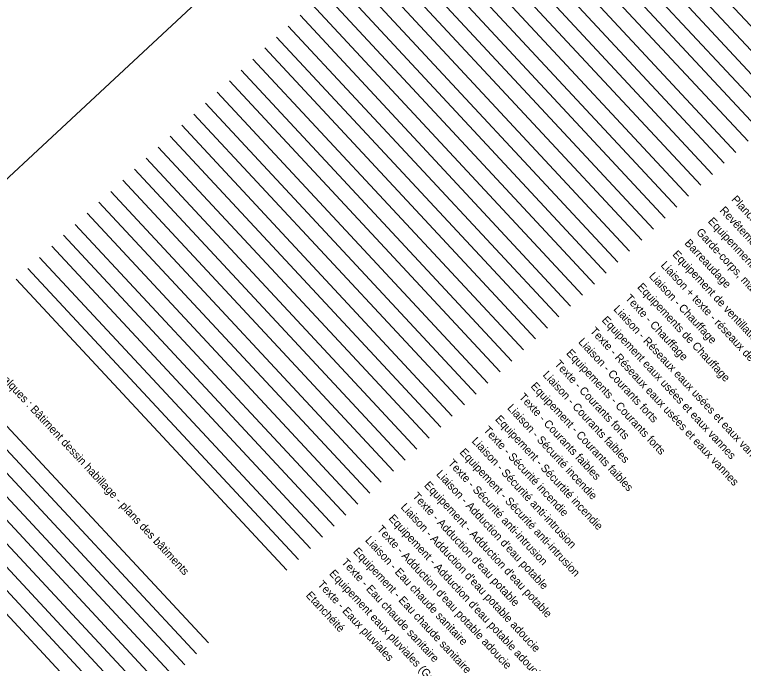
# Model space of a CAD drawing. Extents: x 704383 to 706615, y 7057567 to 7059313.
# Drawn here: x 706521.46 to 706566.99, y 7057633.3 to 7057673.83 of the extents above; entities that cross this region are included whole.
import ezdxf

# ---------------------------------------------------------------- set-up
doc = ezdxf.new("R2010")
doc.units = 0
for name, color, linetype in [('BAT_DH_CALEPINAGE_FACADE', 7, 'Continuous'), ('BAT_DH_COTATION', 7, 'Continuous'), ('BAT_DH_COTATION_NGF', 7, 'Continuous'), ('BAT_DH_EQUIP INTERIEUR', 7, 'Continuous'), ('BAT_DH_HACHURE-MOTIF', 7, 'Continuous'), ('BAT_DH_PERSONNAGE_VEHICULES', 7, 'Continuous'), ('BAT_DH_TEXTE', 7, 'Continuous'), ('BAT_DH_TRAIT CONSTRUCTION', 7, 'Continuous'), ('BAT_DH_TRAIT DE COUPE', 7, 'Continuous'), ('DH_CADRE -CARTOUCHE', 7, 'Continuous'), ('GO_COUVERTURE', 7, 'Continuous'), ('SO_AEP_AD_EQUIP', 7, 'Continuous'), ('SO_AEP_AD_LIAISON', 7, 'Continuous'), ('SO_AEP_AD_TEXTE', 7, 'Continuous'), ('SO_AEP_EQUIP', 7, 'Continuous'), ('SO_AEP_LIAISON', 7, 'Continuous'), ('SO_AEP_TEXTE', 7, 'Continuous'), ('SO_ANTI_INTRUSION_EQUIP', 7, 'Continuous'), ('SO_ANTI_INTRUSION_LIAISON', 7, 'Continuous'), ('SO_ANTI_INTRUSION_TEXTE', 7, 'Continuous'), ('SO_BARREAUDAGE', 7, 'Continuous'), ('SO_CHAUFFAGE_EQUIP', 7, 'Continuous'), ('SO_CHAUFFAGE_LIAISON', 7, 'Continuous'), ('SO_CHAUFFAGE_TEXTE', 7, 'Continuous'), ('SO_ECS_EQUIP', 7, 'Continuous'), ('SO_ECS_LIAISON', 7, 'Continuous'), ('SO_ECS_TEXTE', 7, 'Continuous'), ('SO_ELEC_C_FAIBLES_EQUIP', 7, 'Continuous'), ('SO_ELEC_C_FAIBLES_LIAISON', 7, 'Continuous'), ('SO_ELEC_C_FAIBLES_TEXTE', 7, 'Continuous'), ('SO_ELEC_C_FORTS_EQUIP', 7, 'Continuous'), ('SO_ELEC_C_FORTS_LIAISON', 7, 'Continuous'), ('SO_ELEC_C_FORTS_TEXTE', 7, 'Continuous'), ('SO_EP_EQUIP', 7, 'Continuous'), ('SO_EP_TEXTE', 7, 'Continuous'), ('SO_EU_EV_EQUIP', 7, 'Continuous'), ('SO_EU_EV_LIAISON', 7, 'Continuous'), ('SO_EU_EV_TEXTE', 7, 'Continuous'), ('SO_GARDE_CORPS', 7, 'Continuous'), ('SO_MENUISERIE DIVERS_TEXTE', 7, 'Continuous'), ('SO_MENUISERIE EXT_ EQUIP', 7, 'Continuous'), ('SO_MENUISERIE EXT_TEXTE', 7, 'Continuous'), ('SO_MENUISERIE EXT_TYPE', 7, 'Continuous'), ('SO_MENUISERIE INT_ EQUIP', 7, 'Continuous'), ('SO_MENUISERIE INT_TEXTE', 7, 'Continuous'), ('SO_MENUISERIE INT_TYPE', 7, 'Continuous'), ('SO_PLAFOND', 7, 'Continuous'), ('SO_PLANCHER TECHNIQUE', 7, 'Continuous'), ('SO_REVETEMENT_SOL_MUR', 7, 'Continuous'), ('SO_SANITAIRE', 7, 'Continuous'), ('SO_SECU_INCENDIE_EQUIP', 7, 'Continuous'), ('SO_SECU_INCENDIE_LIAISON', 7, 'Continuous'), ('SO_SECU_INCENDIE_TEXTE', 7, 'Continuous'), ('SO_VMC_CVC_CTA_EQUIP', 7, 'Continuous'), ('SO_VMC_CVC_CTA_RES-TEXTE', 7, 'Continuous')]:
    doc.layers.add(name, color=color, linetype=linetype)

msp = doc.modelspace()

# ---------------------------------------------------------------- linework, layer by layer
at = {"layer": 'BAT_DH_CALEPINAGE_FACADE'}
msp.add_line((706516.66, 7057652.746), (706533.566, 7057634.574), dxfattribs=at)
at = {"layer": 'BAT_DH_COTATION'}
msp.add_line((706515.927, 7057652.065), (706532.833, 7057633.893), dxfattribs=at)
at = {"layer": 'BAT_DH_COTATION_NGF'}
msp.add_line((706515.195, 7057651.383), (706532.101, 7057633.211), dxfattribs=at)
at = {"layer": 'BAT_DH_EQUIP INTERIEUR'}
msp.add_line((706514.463, 7057650.702), (706531.369, 7057632.53), dxfattribs=at)
at = {"layer": 'BAT_DH_HACHURE-MOTIF'}
msp.add_line((706513.731, 7057650.021), (706530.637, 7057631.849), dxfattribs=at)
at = {"layer": 'BAT_DH_PERSONNAGE_VEHICULES'}
msp.add_line((706512.999, 7057649.34), (706529.905, 7057631.168), dxfattribs=at)
at = {"layer": 'BAT_DH_TEXTE'}
msp.add_line((706512.267, 7057648.659), (706529.173, 7057630.487), dxfattribs=at)
at = {"layer": 'BAT_DH_TRAIT CONSTRUCTION'}
msp.add_line((706511.534, 7057647.978), (706528.441, 7057629.806), dxfattribs=at)
at = {"layer": 'BAT_DH_TRAIT DE COUPE'}
msp.add_line((706510.802, 7057647.297), (706527.708, 7057629.124), dxfattribs=at)
at = {"layer": 'DH_CADRE -CARTOUCHE'}
msp.add_lwpolyline([(706573.792, 7057712.707), (706614.66, 7057668.778), (706534.124, 7057593.852), (706493.255, 7057637.781)], close=True, dxfattribs=at)
at = {"layer": 'GO_COUVERTURE'}
msp.add_line((706521.562, 7057657.297), (706538.475, 7057639.118), dxfattribs=at)
at = {"layer": 'SO_AEP_AD_EQUIP'}
msp.add_line((706526.733, 7057662.107), (706543.645, 7057643.928), dxfattribs=at)
at = {"layer": 'SO_AEP_AD_LIAISON'}
msp.add_line((706527.465, 7057662.788), (706544.368, 7057644.62), dxfattribs=at)
at = {"layer": 'SO_AEP_AD_TEXTE'}
msp.add_line((706526.001, 7057661.426), (706542.913, 7057643.247), dxfattribs=at)
at = {"layer": 'SO_AEP_EQUIP'}
msp.add_line((706528.952, 7057664.172), (706545.865, 7057645.993), dxfattribs=at)
at = {"layer": 'SO_AEP_LIAISON'}
msp.add_line((706529.684, 7057664.853), (706546.587, 7057646.685), dxfattribs=at)
at = {"layer": 'SO_AEP_TEXTE'}
msp.add_line((706528.22, 7057663.491), (706545.132, 7057645.312), dxfattribs=at)
at = {"layer": 'SO_ANTI_INTRUSION_EQUIP'}
msp.add_line((706531.171, 7057666.236), (706548.084, 7057648.058), dxfattribs=at)
at = {"layer": 'SO_ANTI_INTRUSION_LIAISON'}
msp.add_line((706531.903, 7057666.918), (706548.806, 7057648.75), dxfattribs=at)
at = {"layer": 'SO_ANTI_INTRUSION_TEXTE'}
msp.add_line((706530.439, 7057665.555), (706547.352, 7057647.376), dxfattribs=at)
at = {"layer": 'SO_BARREAUDAGE'}
msp.add_line((706545.196, 7057679.284), (706562.098, 7057661.116), dxfattribs=at)
at = {"layer": 'SO_CHAUFFAGE_EQUIP'}
msp.add_line((706542.244, 7057676.538), (706559.147, 7057658.37), dxfattribs=at)
at = {"layer": 'SO_CHAUFFAGE_LIAISON'}
msp.add_line((706542.976, 7057677.219), (706559.879, 7057659.051), dxfattribs=at)
at = {"layer": 'SO_CHAUFFAGE_TEXTE'}
msp.add_line((706541.512, 7057675.857), (706558.425, 7057657.678), dxfattribs=at)
at = {"layer": 'SO_ECS_EQUIP'}
msp.add_line((706524.514, 7057660.043), (706541.426, 7057641.864), dxfattribs=at)
at = {"layer": 'SO_ECS_LIAISON'}
msp.add_line((706525.246, 7057660.724), (706542.148, 7057642.556), dxfattribs=at)
at = {"layer": 'SO_ECS_TEXTE'}
msp.add_line((706523.782, 7057659.362), (706540.694, 7057641.183), dxfattribs=at)
at = {"layer": 'SO_ELEC_C_FAIBLES_EQUIP'}
msp.add_line((706535.61, 7057670.366), (706552.522, 7057652.187), dxfattribs=at)
at = {"layer": 'SO_ELEC_C_FAIBLES_LIAISON'}
msp.add_line((706536.342, 7057671.047), (706553.244, 7057652.879), dxfattribs=at)
at = {"layer": 'SO_ELEC_C_FAIBLES_TEXTE'}
msp.add_line((706534.877, 7057669.684), (706551.79, 7057651.506), dxfattribs=at)
at = {"layer": 'SO_ELEC_C_FORTS_EQUIP'}
msp.add_line((706537.829, 7057672.43), (706554.741, 7057654.251), dxfattribs=at)
at = {"layer": 'SO_ELEC_C_FORTS_LIAISON'}
msp.add_line((706538.561, 7057673.111), (706555.463, 7057654.943), dxfattribs=at)
at = {"layer": 'SO_ELEC_C_FORTS_TEXTE'}
msp.add_line((706537.097, 7057671.749), (706554.009, 7057653.57), dxfattribs=at)
at = {"layer": 'SO_EP_EQUIP'}
msp.add_line((706523.027, 7057658.659), (706539.939, 7057640.48), dxfattribs=at)
at = {"layer": 'SO_EP_TEXTE'}
msp.add_line((706522.295, 7057657.978), (706539.207, 7057639.799), dxfattribs=at)
at = {"layer": 'SO_EU_EV_EQUIP'}
msp.add_line((706540.025, 7057674.474), (706556.928, 7057656.305), dxfattribs=at)
at = {"layer": 'SO_EU_EV_LIAISON'}
msp.add_line((706540.78, 7057675.176), (706557.693, 7057656.997), dxfattribs=at)
at = {"layer": 'SO_EU_EV_TEXTE'}
msp.add_line((706539.293, 7057673.792), (706556.195, 7057655.624), dxfattribs=at)
at = {"layer": 'SO_GARDE_CORPS'}
msp.add_line((706545.928, 7057679.965), (706562.83, 7057661.797), dxfattribs=at)
at = {"layer": 'SO_MENUISERIE DIVERS_TEXTE'}
msp.add_line((706554.05, 7057687.521), (706570.962, 7057669.342), dxfattribs=at)
at = {"layer": 'SO_MENUISERIE EXT_ EQUIP'}
msp.add_line((706553.295, 7057686.819), (706570.197, 7057668.651), dxfattribs=at)
at = {"layer": 'SO_MENUISERIE EXT_TEXTE'}
msp.add_line((706552.563, 7057686.138), (706569.465, 7057667.969), dxfattribs=at)
at = {"layer": 'SO_MENUISERIE EXT_TYPE'}
msp.add_line((706551.83, 7057685.456), (706568.733, 7057667.288), dxfattribs=at)
at = {"layer": 'SO_MENUISERIE INT_ EQUIP'}
msp.add_line((706551.098, 7057684.775), (706568.011, 7057666.596), dxfattribs=at)
at = {"layer": 'SO_MENUISERIE INT_TEXTE'}
msp.add_line((706550.366, 7057684.094), (706567.279, 7057665.915), dxfattribs=at)
at = {"layer": 'SO_MENUISERIE INT_TYPE'}
msp.add_line((706549.611, 7057683.392), (706566.514, 7057665.224), dxfattribs=at)
at = {"layer": 'SO_PLAFOND'}
msp.add_line((706548.879, 7057682.711), (706565.782, 7057664.543), dxfattribs=at)
at = {"layer": 'SO_PLANCHER TECHNIQUE'}
msp.add_line((706548.147, 7057682.03), (706565.059, 7057663.851), dxfattribs=at)
at = {"layer": 'SO_REVETEMENT_SOL_MUR'}
msp.add_line((706547.415, 7057681.348), (706564.327, 7057663.17), dxfattribs=at)
at = {"layer": 'SO_SANITAIRE'}
msp.add_line((706546.66, 7057680.646), (706563.562, 7057662.478), dxfattribs=at)
at = {"layer": 'SO_SECU_INCENDIE_EQUIP'}
msp.add_line((706533.39, 7057668.301), (706550.303, 7057650.122), dxfattribs=at)
at = {"layer": 'SO_SECU_INCENDIE_LIAISON'}
msp.add_line((706534.123, 7057668.982), (706551.025, 7057650.814), dxfattribs=at)
at = {"layer": 'SO_SECU_INCENDIE_TEXTE'}
msp.add_line((706532.658, 7057667.62), (706549.571, 7057649.441), dxfattribs=at)
at = {"layer": 'SO_VMC_CVC_CTA_EQUIP'}
msp.add_line((706544.463, 7057678.603), (706561.376, 7057660.424), dxfattribs=at)
at = {"layer": 'SO_VMC_CVC_CTA_RES-TEXTE'}
msp.add_line((706543.731, 7057677.922), (706560.644, 7057659.743), dxfattribs=at)

# ---------------------------------------------------------------- texts
at = {"layer": 'DH_CADRE -CARTOUCHE'}
msp.add_text(' Calques : Bâtiment dessin habillage - plans des bâtiments', height=0.5, rotation=312.9332, dxfattribs=at).set_placement((706520.234, 7057651.473))
at = {"layer": 'GO_COUVERTURE'}
msp.add_text('Etanchéité', height=0.5, rotation=312.9332, dxfattribs=at).set_placement((706539.622, 7057637.518))
at = {"layer": 'SO_AEP_AD_EQUIP'}
msp.add_text("Equipement - Adduction d'eau potable adoucie", height=0.5, rotation=312.9332, dxfattribs=at).set_placement((706544.793, 7057642.328))
at = {"layer": 'SO_AEP_AD_LIAISON'}
msp.add_text("Liaison - Adduction d'eau potable adoucie", height=0.5, rotation=312.9332, dxfattribs=at).set_placement((706545.548, 7057643.03))
at = {"layer": 'SO_AEP_AD_TEXTE'}
msp.add_text("Texte - Adduction d'eau potable adoucie", height=0.5, rotation=312.9332, dxfattribs=at).set_placement((706544.061, 7057641.647))
at = {"layer": 'SO_AEP_EQUIP'}
msp.add_text("Equipement - Adduction d'eau potable", height=0.5, rotation=312.9332, dxfattribs=at).set_placement((706547.012, 7057644.393))
at = {"layer": 'SO_AEP_LIAISON'}
msp.add_text("Liaison - Adduction d'eau potable", height=0.5, rotation=312.9332, dxfattribs=at).set_placement((706547.767, 7057645.095))
at = {"layer": 'SO_AEP_TEXTE'}
msp.add_text("Texte - Adduction d'eau potable", height=0.5, rotation=312.9332, dxfattribs=at).set_placement((706546.28, 7057643.711))
at = {"layer": 'SO_ANTI_INTRUSION_EQUIP'}
msp.add_text('Equipement - Sécurité anti-intrusion', height=0.5, rotation=312.9332, dxfattribs=at).set_placement((706549.231, 7057646.457))
at = {"layer": 'SO_ANTI_INTRUSION_LIAISON'}
msp.add_text('Liaison - Sécurité anti-intrusion', height=0.5, rotation=312.9332, dxfattribs=at).set_placement((706549.986, 7057647.159))
at = {"layer": 'SO_ANTI_INTRUSION_TEXTE'}
msp.add_text('Texte - Sécurité anti-intrusion', height=0.5, rotation=312.9332, dxfattribs=at).set_placement((706548.499, 7057645.776))
at = {"layer": 'SO_BARREAUDAGE'}
msp.add_text('Barreaudage', height=0.5, rotation=312.9332, dxfattribs=at).set_placement((706563.278, 7057659.526))
at = {"layer": 'SO_CHAUFFAGE_EQUIP'}
msp.add_text('Equipements de Chauffage', height=0.5, rotation=312.9332, dxfattribs=at).set_placement((706560.327, 7057656.78))
at = {"layer": 'SO_CHAUFFAGE_LIAISON'}
msp.add_text('Liaison - Chauffage', height=0.5, rotation=312.9332, dxfattribs=at).set_placement((706561.059, 7057657.461))
at = {"layer": 'SO_CHAUFFAGE_TEXTE'}
msp.add_text('Texte - Chauffage', height=0.5, rotation=312.9332, dxfattribs=at).set_placement((706559.572, 7057656.078))
at = {"layer": 'SO_ECS_EQUIP'}
msp.add_text('Equipement - Eau chaude sanitaire', height=0.5, rotation=312.9332, dxfattribs=at).set_placement((706542.574, 7057640.263))
at = {"layer": 'SO_ECS_LIAISON'}
msp.add_text('Liaison - Eau chaude sanitaire', height=0.5, rotation=312.9332, dxfattribs=at).set_placement((706543.329, 7057640.966))
at = {"layer": 'SO_ECS_TEXTE'}
msp.add_text('Texte - Eau chaude sanitaire', height=0.5, rotation=312.9332, dxfattribs=at).set_placement((706541.842, 7057639.582))
at = {"layer": 'SO_ELEC_C_FAIBLES_EQUIP'}
msp.add_text('Equipement - Courants faibles', height=0.5, rotation=312.9332, dxfattribs=at).set_placement((706553.67, 7057650.586))
at = {"layer": 'SO_ELEC_C_FAIBLES_LIAISON'}
msp.add_text('Liaison - Courants faibles', height=0.5, rotation=312.9332, dxfattribs=at).set_placement((706554.424, 7057651.289))
at = {"layer": 'SO_ELEC_C_FAIBLES_TEXTE'}
msp.add_text('Texte - Courants faibles', height=0.5, rotation=312.9332, dxfattribs=at).set_placement((706552.937, 7057649.905))
at = {"layer": 'SO_ELEC_C_FORTS_EQUIP'}
msp.add_text('Equipements - Courants forts', height=0.5, rotation=312.9332, dxfattribs=at).set_placement((706555.889, 7057652.651))
at = {"layer": 'SO_ELEC_C_FORTS_LIAISON'}
msp.add_text('Liaison - Courants forts', height=0.5, rotation=312.9332, dxfattribs=at).set_placement((706556.644, 7057653.353))
at = {"layer": 'SO_ELEC_C_FORTS_TEXTE'}
msp.add_text('Texte - Courants forts', height=0.5, rotation=312.9332, dxfattribs=at).set_placement((706555.157, 7057651.97))
at = {"layer": 'SO_EP_EQUIP'}
msp.add_text('Equipement eaux pluviales (Gouttières, chéneaux, descentes EP...)', height=0.5, rotation=312.9332, dxfattribs=at).set_placement((706541.087, 7057638.88))
at = {"layer": 'SO_EP_TEXTE'}
msp.add_text('Texte - Eaux pluviales', height=0.5, rotation=312.9332, dxfattribs=at).set_placement((706540.355, 7057638.199))
at = {"layer": 'SO_EU_EV_EQUIP'}
msp.add_text('Equipement eaux usées et eaux vannes', height=0.5, rotation=312.9332, dxfattribs=at).set_placement((706558.108, 7057654.715))
at = {"layer": 'SO_EU_EV_LIAISON'}
msp.add_text('Liaison - Réseaux eaux usées et eaux vannes', height=0.5, rotation=312.9332, dxfattribs=at).set_placement((706558.84, 7057655.397))
at = {"layer": 'SO_EU_EV_TEXTE'}
msp.add_text('Texte - Réseaux eaux usées et eaux vannes', height=0.5, rotation=312.9332, dxfattribs=at).set_placement((706557.376, 7057654.034))
at = {"layer": 'SO_GARDE_CORPS'}
msp.add_text('Garde-corps, main courante', height=0.5, rotation=312.9332, dxfattribs=at).set_placement((706564.01, 7057660.207))
at = {"layer": 'SO_PLANCHER TECHNIQUE'}
msp.add_text('Plancher technique', height=0.5, rotation=312.9332, dxfattribs=at).set_placement((706566.207, 7057662.25))
at = {"layer": 'SO_REVETEMENT_SOL_MUR'}
msp.add_text('Revêtement des sols, des murs', height=0.5, rotation=312.9332, dxfattribs=at).set_placement((706565.475, 7057661.569))
at = {"layer": 'SO_SANITAIRE'}
msp.add_text('Equipenments sanitaires', height=0.5, rotation=312.9332, dxfattribs=at).set_placement((706564.743, 7057660.888))
at = {"layer": 'SO_SECU_INCENDIE_EQUIP'}
msp.add_text('Equipement - Sécurtité incendie', height=0.5, rotation=312.9332, dxfattribs=at).set_placement((706551.45, 7057648.522))
at = {"layer": 'SO_SECU_INCENDIE_LIAISON'}
msp.add_text('Liaison - Sécurité incendie', height=0.5, rotation=312.9332, dxfattribs=at).set_placement((706552.205, 7057649.224))
at = {"layer": 'SO_SECU_INCENDIE_TEXTE'}
msp.add_text('Texte - Sécurité incendie', height=0.5, rotation=312.9332, dxfattribs=at).set_placement((706550.718, 7057647.841))
at = {"layer": 'SO_VMC_CVC_CTA_EQUIP'}
msp.add_text('Equipement de ventillation (VMC, CTA,...)', height=0.5, rotation=312.9332, dxfattribs=at).set_placement((706562.523, 7057658.823))
at = {"layer": 'SO_VMC_CVC_CTA_RES-TEXTE'}
msp.add_text('Liaison + texte - réseaux de ventilation (Extraction, soufflage)', height=0.5, rotation=312.9332, dxfattribs=at).set_placement((706561.791, 7057658.142))

doc.saveas('drawing.dxf')
